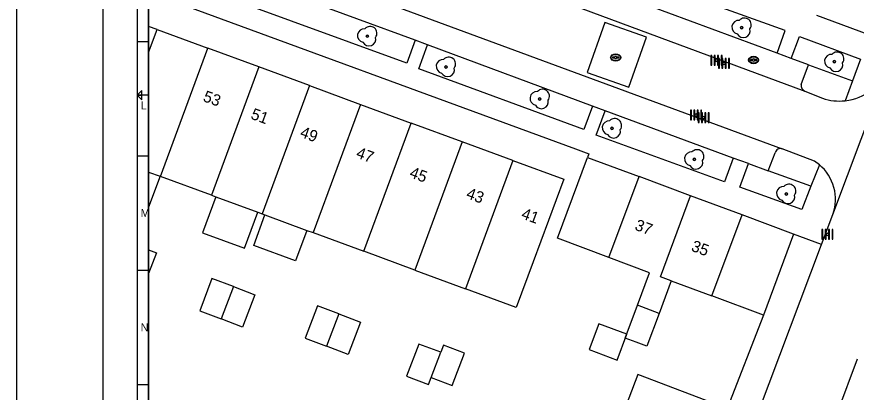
# Model space of a CAD drawing. Extents: x 192664 to 192925, y 446334 to 446521.
# Drawn here: x 192664.2 to 192737.6, y 446377 to 446409.8 of the extents above; entities that cross this region are included whole.
import ezdxf

# ---------------------------------------------------------------- set-up
doc = ezdxf.new("R2010")
doc.units = 0
for name, color, linetype in [('1010 viewport', 7, 'Continuous'), ('boom', 7, 'Continuous'), ('grens niveau plus 1', 7, 'Continuous'), ('huisnummerreeks BGT', 7, 'Continuous'), ('inspectie-   rioolput', 7, 'Continuous'), ('kant open verharding', 7, 'Continuous'), ('kant verharding', 7, 'Continuous'), ('kolk', 7, 'Continuous'), ('Luifel', 7, 'Continuous'), ('pand op maaiveld vlak', 7, 'Continuous'), ('verkeerseiland - berm', 7, 'Continuous'), ('X-XX-AL-TEKENBLAD-S', 7, 'Continuous'), ('X-XX-AL-TEKENBLAD_KADER-G', 7, 'Continuous')]:
    doc.layers.add(name, color=color, linetype=linetype)

msp = doc.modelspace()

# ---------------------------------------------------------------- linework, layer by layer
at = {"layer": '1010 viewport'}
msp.add_lwpolyline([(192675.743, 446509.756), (192860.643, 446509.756), (192860.643, 446345.556), (192675.743, 446345.556)], close=True, dxfattribs=at)
at = {"layer": 'boom'}
for centre in [(192727.554, 446408.855), (192694.841, 446408.12), (192735.654, 446405.881), (192701.719, 446405.432), (192709.917, 446402.624), (192716.227, 446400.059), (192723.418, 446397.341), (192731.456, 446394.317)]:
    msp.add_circle(centre, 0.1, dxfattribs=at)
for centre, radius, start, end in [((192727.304, 446408.905), 0.6, 85.13702, 257.75442), ((192727.804, 446409.105), 0.6, 323.54458, 138.4658), ((192694.591, 446408.17), 0.6, 85.13702, 257.75442), ((192695.091, 446408.37), 0.6, 323.54458, 138.4658), ((192727.704, 446408.605), 0.6, 208.50578, 13.83556), ((192727.554, 446408.855), 0.1, 0, 180), ((192727.554, 446408.855), 0.1, 180, 0), ((192694.991, 446407.87), 0.6, 208.50578, 13.83556), ((192694.841, 446408.12), 0.1, 0, 180), ((192694.841, 446408.12), 0.1, 180, 0), ((192735.404, 446405.931), 0.6, 85.13702, 257.75442), ((192735.904, 446406.131), 0.6, 323.54458, 138.4658), ((192701.469, 446405.482), 0.6, 85.13702, 257.75442), ((192701.969, 446405.682), 0.6, 323.54458, 138.4658), ((192735.804, 446405.631), 0.6, 208.50578, 13.83556), ((192735.654, 446405.881), 0.1, 0, 180), ((192735.654, 446405.881), 0.1, 180, 0), ((192701.869, 446405.182), 0.6, 208.50578, 13.83556), ((192701.719, 446405.432), 0.1, 0, 180), ((192701.719, 446405.432), 0.1, 180, 0), ((192710.167, 446402.874), 0.6, 323.54458, 138.4658), ((192709.667, 446402.674), 0.6, 85.13702, 257.75442), ((192709.917, 446402.624), 0.1, 0, 180), ((192710.067, 446402.374), 0.6, 208.50578, 13.83556), ((192709.917, 446402.624), 0.1, 180, 0), ((192715.977, 446400.109), 0.6, 85.13702, 257.75442), ((192716.477, 446400.309), 0.6, 323.54458, 138.4658), ((192716.377, 446399.809), 0.6, 208.50578, 13.83556), ((192716.227, 446400.059), 0.1, 0, 180), ((192716.227, 446400.059), 0.1, 180, 0), ((192723.168, 446397.391), 0.6, 85.13702, 257.75442), ((192723.668, 446397.591), 0.6, 323.54458, 138.4658), ((192723.568, 446397.091), 0.6, 208.50578, 13.83556), ((192723.418, 446397.341), 0.1, 0, 180), ((192723.418, 446397.341), 0.1, 180, 0), ((192731.206, 446394.367), 0.6, 85.13702, 257.75442), ((192731.706, 446394.567), 0.6, 323.54458, 138.4658), ((192731.606, 446394.067), 0.6, 208.50578, 13.83556), ((192731.456, 446394.317), 0.1, 0, 180), ((192731.456, 446394.317), 0.1, 180, 0)]:
    msp.add_arc(centre, radius, start, end, dxfattribs=at)
at = {"layer": 'grens niveau plus 1'}
msp.add_lwpolyline([(192717.516, 446382.047), (192715.072, 446382.958), (192714.229, 446380.696), (192716.674, 446379.786), (192717.516, 446382.047)], dxfattribs=at)
at = {"layer": 'inspectie-   rioolput'}
for p, q in [((192716.461, 446406.292), (192716.304, 446406.292)), ((192716.304, 446406.218), (192716.461, 446406.218)), ((192716.804, 446406.292), (192716.647, 446406.292)), ((192716.647, 446406.218), (192716.804, 446406.218)), ((192728.513, 446406.072), (192728.356, 446406.072)), ((192728.356, 446405.997), (192728.513, 446405.997)), ((192728.856, 446406.072), (192728.699, 446406.072)), ((192728.699, 446405.997), (192728.856, 446405.997))]:
    msp.add_line(p, q, dxfattribs=at)
for centre, radius, start, end in [((192716.554, 446406.255), 0.1, 0, 180), ((192716.304, 446406.255), 0.0375, 90, 270), ((192716.554, 446406.255), 0.1, 157.97569, 180), ((192716.554, 446406.255), 0.1, 180, 202.02431), ((192716.554, 446406.255), 0.1, 180, 0), ((192716.554, 446406.255), 0.1, 0, 22.02431), ((192716.554, 446406.255), 0.1, 337.97569, 0), ((192716.804, 446406.255), 0.0375, 270, 90), ((192728.356, 446406.034), 0.0375, 90, 270), ((192728.606, 446406.034), 0.1, 0, 180), ((192728.606, 446406.034), 0.1, 157.97569, 180), ((192728.606, 446406.034), 0.1, 180, 202.02431), ((192728.606, 446406.034), 0.1, 180, 0), ((192728.606, 446406.034), 0.1, 0, 22.02431), ((192728.606, 446406.034), 0.1, 337.97569, 0), ((192728.856, 446406.034), 0.0375, 270, 90)]:
    msp.add_arc(centre, radius, start, end, dxfattribs=at)
for centre, major_axis, ratio in [((192716.554, 446406.255), (-0.442, 0), 0.73911), ((192716.554, 446406.255), (-0.392, 0), 0.689655), ((192728.606, 446406.034), (-0.442, 0), 0.73911), ((192728.606, 446406.034), (-0.392, 0), 0.689655)]:
    msp.add_ellipse(centre, major_axis=major_axis, ratio=ratio, dxfattribs=at)
at = {"layer": 'kant open verharding'}
for p, q in [((192734.543, 446389.88), (192735.54, 446392.53)), ((192734.543, 446389.88), (192732.105, 446390.808)), ((192728.589, 446374.052), (192734.543, 446389.88)), ((192729.467, 446383.724), (192726.296, 446375.548))]:
    msp.add_line(p, q, dxfattribs=at)
for points in [[(192675.743, 446411.995), (192713.029, 446398.263), (192714.204, 446397.83), (192714.097, 446397.514)], [(192719.251, 446408.036), (192715.613, 446409.33), (192714.055, 446404.947), (192717.693, 446403.653), (192719.251, 446408.036)]]:
    msp.add_lwpolyline(points, dxfattribs=at)
for centre, radius, start, end in [((192736.087, 446407.003), 4.557, 276.55625, 339.08322), ((192731.81, 446393.843), 3.954, 340.60439, 49.92149)]:
    msp.add_arc(centre, radius, start, end, dxfattribs=at)
at = {"layer": 'kant verharding'}
for p, q in [((192675.743, 446424.623), (192733.082, 446403.313)), ((192675.743, 446418.762), (192731.114, 446398.266)), ((192700.122, 446407.353), (192699.029, 446407.759)), ((192731.902, 446406.177), (192730.661, 446406.636)), ((192735.54, 446392.53), (192740.343, 446405.376)), ((192715.622, 446401.596), (192714.516, 446402.006)), ((192728.147, 446396.977), (192726.814, 446397.454)), ((192737.657, 446379.855), (192731.919, 446364.598))]:
    msp.add_line(p, q, dxfattribs=at)
at = {"layer": 'kolk'}
for points in [[(192724.953, 446406.009), (192724.953, 446406.434), (192724.868, 446406.434), (192724.868, 446406.009), (192724.868, 446405.584), (192724.953, 446405.584)], [(192725.251, 446406.009), (192725.251, 446406.434), (192725.166, 446406.434), (192725.166, 446406.009), (192725.166, 446405.584), (192725.251, 446405.584)], [(192725.548, 446406.009), (192725.548, 446406.434), (192725.463, 446406.434), (192725.463, 446406.009), (192725.463, 446405.584), (192725.548, 446405.584)], [(192725.846, 446406.009), (192725.846, 446406.434), (192725.761, 446406.434), (192725.761, 446406.009), (192725.761, 446405.584), (192725.846, 446405.584)], [(192725.613, 446405.743), (192725.613, 446406.168), (192725.528, 446406.168), (192725.528, 446405.743), (192725.528, 446405.318), (192725.613, 446405.318)], [(192725.911, 446405.743), (192725.911, 446406.168), (192725.826, 446406.168), (192725.826, 446405.743), (192725.826, 446405.318), (192725.911, 446405.318)], [(192726.208, 446405.743), (192726.208, 446406.168), (192726.123, 446406.168), (192726.123, 446405.743), (192726.123, 446405.318), (192726.208, 446405.318)], [(192726.506, 446405.743), (192726.506, 446406.168), (192726.421, 446406.168), (192726.421, 446405.743), (192726.421, 446405.318), (192726.506, 446405.318)], [(192723.173, 446401.218), (192723.173, 446401.643), (192723.088, 446401.643), (192723.088, 446401.218), (192723.088, 446400.793), (192723.173, 446400.793)], [(192723.471, 446401.218), (192723.471, 446401.643), (192723.386, 446401.643), (192723.386, 446401.218), (192723.386, 446400.793), (192723.471, 446400.793)], [(192723.768, 446401.218), (192723.768, 446401.643), (192723.683, 446401.643), (192723.683, 446401.218), (192723.683, 446400.793), (192723.768, 446400.793)], [(192723.836, 446401.002), (192723.836, 446401.427), (192723.751, 446401.427), (192723.751, 446401.002), (192723.751, 446400.577), (192723.836, 446400.577)], [(192724.066, 446401.218), (192724.066, 446401.643), (192723.981, 446401.643), (192723.981, 446401.218), (192723.981, 446400.793), (192724.066, 446400.793)], [(192724.134, 446401.002), (192724.134, 446401.427), (192724.049, 446401.427), (192724.049, 446401.002), (192724.049, 446400.577), (192724.134, 446400.577)], [(192724.431, 446401.002), (192724.431, 446401.427), (192724.346, 446401.427), (192724.346, 446401.002), (192724.346, 446400.577), (192724.431, 446400.577)], [(192724.729, 446401.002), (192724.729, 446401.427), (192724.644, 446401.427), (192724.644, 446401.002), (192724.644, 446400.577), (192724.729, 446400.577)], [(192734.65, 446390.779), (192734.65, 446391.204), (192734.565, 446391.204), (192734.565, 446390.779), (192734.565, 446390.354), (192734.65, 446390.354)], [(192734.948, 446390.779), (192734.948, 446391.204), (192734.863, 446391.204), (192734.863, 446390.779), (192734.863, 446390.354), (192734.948, 446390.354)], [(192735.245, 446390.779), (192735.245, 446391.204), (192735.16, 446391.204), (192735.16, 446390.779), (192735.16, 446390.354), (192735.245, 446390.354)], [(192735.543, 446390.779), (192735.543, 446391.204), (192735.458, 446391.204), (192735.458, 446390.779), (192735.458, 446390.354), (192735.543, 446390.354)]]:
    msp.add_lwpolyline(points, close=True, dxfattribs=at)
for centre, start, end in [((192725.357, 446406.009), 0, 180), ((192725.357, 446406.009), 180, 0), ((192726.017, 446405.743), 0, 180), ((192726.017, 446405.743), 180, 0), ((192723.577, 446401.218), 0, 180), ((192723.577, 446401.218), 180, 0), ((192724.24, 446401.002), 0, 180), ((192724.24, 446401.002), 180, 0), ((192735.054, 446390.779), 0, 180), ((192735.054, 446390.779), 180, 0)]:
    msp.add_arc(centre, 0.1, start, end, dxfattribs=at)
at = {"layer": 'Luifel'}
msp.add_line((192676.742, 446395.864), (192675.743, 446393.155), dxfattribs=at)
for points in [[(192681.619, 446394.065), (192680.458, 446390.919), (192684.13, 446389.564), (192685.291, 446392.711)], [(192689.572, 446391.132), (192688.588, 446388.464), (192684.925, 446389.814), (192685.908, 446392.483)]]:
    msp.add_lwpolyline(points, dxfattribs=at)
at = {"layer": 'pand op maaiveld vlak'}
for p, q in [((192676.487, 446408.706), (192675.743, 446408.98)), ((192675.743, 446406.689), (192676.487, 446408.706)), ((192676.487, 446408.706), (192680.928, 446407.068)), ((192676.789, 446395.847), (192680.928, 446407.068)), ((192685.368, 446405.43), (192680.928, 446407.068)), ((192685.368, 446405.43), (192681.229, 446394.209)), ((192689.808, 446403.792), (192685.368, 446405.43)), ((192689.808, 446403.792), (192685.669, 446392.571)), ((192689.808, 446403.792), (192694.248, 446402.155)), ((192694.248, 446402.155), (192690.11, 446390.934)), ((192694.248, 446402.155), (192698.688, 446400.517)), ((192694.55, 446389.296), (192698.688, 446400.517)), ((192703.129, 446398.879), (192698.688, 446400.517)), ((192703.129, 446398.879), (192698.99, 446387.658)), ((192707.569, 446397.242), (192703.129, 446398.879)), ((192714.097, 446397.514), (192718.599, 446395.838)), ((192707.569, 446397.242), (192703.43, 446386.021)), ((192675.743, 446396.232), (192676.742, 446395.864)), ((192676.742, 446395.864), (192676.789, 446395.847)), ((192681.229, 446394.209), (192676.789, 446395.847)), ((192715.962, 446388.755), (192718.599, 446395.838)), ((192723.101, 446394.161), (192718.599, 446395.838)), ((192681.229, 446394.209), (192681.619, 446394.065)), ((192681.619, 446394.065), (192685.291, 446392.711)), ((192727.603, 446392.484), (192723.101, 446394.161)), ((192685.291, 446392.711), (192685.669, 446392.571)), ((192685.669, 446392.571), (192685.908, 446392.483)), ((192685.908, 446392.483), (192689.572, 446391.132)), ((192724.965, 446385.4), (192727.603, 446392.484)), ((192732.105, 446390.808), (192727.603, 446392.484)), ((192689.572, 446391.132), (192690.11, 446390.934)), ((192690.11, 446390.934), (192694.55, 446389.296)), ((192732.105, 446390.808), (192729.467, 446383.724)), ((192698.99, 446387.658), (192694.55, 446389.296)), ((192698.99, 446387.658), (192703.43, 446386.021)), ((192721.407, 446386.724), (192720.343, 446383.867)), ((192721.407, 446386.724), (192724.965, 446385.4)), ((192683.154, 446386.21), (192682.08, 446383.388)), ((192729.467, 446383.724), (192724.965, 446385.4)), ((192720.343, 446383.867), (192718.456, 446384.57)), ((192692.365, 446383.812), (192691.291, 446380.989)), ((192700.434, 446378.254), (192701.268, 446380.461))]:
    msp.add_line(p, q, dxfattribs=at)
for points in [[(192738.776, 446408.675), (192738.63, 446408.277), (192734.126, 446409.932)], [(192715.962, 446388.755), (192711.461, 446390.434), (192714.097, 446397.514)], [(192707.569, 446397.242), (192712.009, 446395.604), (192709.342, 446388.371), (192707.87, 446384.383), (192703.43, 446386.021)], [(192721.407, 446386.724), (192720.462, 446387.076), (192723.101, 446394.161)], [(192675.743, 446389.434), (192676.43, 446389.173), (192675.743, 446387.368)], [(192718.456, 446384.57), (192719.52, 446387.428), (192715.962, 446388.755)], [(192683.154, 446386.21), (192681.275, 446386.925), (192680.201, 446384.102), (192682.08, 446383.388)], [(192683.154, 446386.21), (192685.032, 446385.495), (192683.958, 446382.673), (192682.08, 446383.388)], [(192692.365, 446383.812), (192690.486, 446384.526), (192689.412, 446381.704), (192691.291, 446380.989)], [(192720.343, 446383.867), (192719.279, 446381.008), (192718.334, 446381.36), (192717.391, 446381.711), (192718.456, 446384.57)], [(192692.365, 446383.812), (192694.243, 446383.097), (192693.169, 446380.274), (192691.291, 446380.989)], [(192701.268, 446380.461), (192699.351, 446381.186), (192698.283, 446378.361), (192700.201, 446377.636), (192700.434, 446378.254)], [(192700.434, 446378.254), (192702.277, 446377.557), (192703.344, 446380.382), (192701.502, 446381.078), (192701.268, 446380.461)], [(192726.296, 446375.548), (192718.482, 446378.507), (192716.363, 446372.909)]]:
    msp.add_lwpolyline(points, dxfattribs=at)
at = {"layer": 'verkeerseiland - berm'}
for p, q in [((192699.029, 446407.759), (192683.929, 446413.333)), ((192730.661, 446406.636), (192719.304, 446410.835)), ((192714.516, 446402.006), (192700.122, 446407.353)), ((192733.417, 446405.619), (192731.902, 446406.177)), ((192732.774, 446403.888), (192733.417, 446405.619)), ((192733.417, 446405.619), (192737.245, 446404.209)), ((192737.245, 446404.209), (192736.607, 446402.476)), ((192733.082, 446403.313), (192734.635, 446402.685)), ((192726.814, 446397.454), (192715.622, 446401.596)), ((192729.893, 446396.351), (192730.476, 446397.916)), ((192728.147, 446396.977), (192729.893, 446396.351)), ((192734.356, 446396.869), (192733.62, 446394.998)), ((192733.62, 446394.998), (192729.893, 446396.351))]:
    msp.add_line(p, q, dxfattribs=at)
for points in [[(192699.029, 446407.759), (192698.296, 446405.758), (192683.182, 446411.296), (192683.929, 446413.333)], [(192730.661, 446406.636), (192731.377, 446408.627), (192719.987, 446412.729), (192719.304, 446410.835)], [(192731.902, 446406.177), (192732.604, 446408.083), (192737.948, 446406.115), (192737.245, 446404.209)], [(192714.516, 446402.006), (192713.762, 446399.96), (192699.355, 446405.274), (192700.122, 446407.353)], [(192726.814, 446397.454), (192726.067, 446395.39), (192714.846, 446399.456), (192715.622, 446401.596)], [(192734.356, 446396.869), (192733.926, 446397.184), (192731.114, 446398.266)], [(192733.62, 446394.998), (192732.813, 446392.945), (192727.395, 446394.907), (192728.147, 446396.977)]]:
    msp.add_lwpolyline(points, dxfattribs=at)
for centre, radius, start, end in [((192733.31, 446403.805), 0.543, 171.2346, 245.11705), ((192736.09, 446407.009), 4.562, 251.39698, 276.50335), ((192730.97, 446397.772), 0.514, 73.73617, 163.76124)]:
    msp.add_arc(centre, radius, start, end, dxfattribs=at)
at = {"layer": 'X-XX-AL-TEKENBLAD-S'}
for p, q in [((192671.743, 446511.756), (192671.743, 446343.556)), ((192674.743, 446510.756), (192674.743, 446344.556)), ((192674.743, 446407.656), (192675.743, 446407.656)), ((192675.143, 446402.956), (192674.743, 446402.956)), ((192674.743, 446402.956), (192675.143, 446402.956)), ((192675.743, 446402.956), (192674.743, 446402.956)), ((192674.743, 446397.656), (192675.743, 446397.656)), ((192674.743, 446387.656), (192675.743, 446387.656)), ((192674.743, 446377.656), (192675.743, 446377.656))]:
    msp.add_line(p, q, dxfattribs=at)
msp.add_lwpolyline([(192675.743, 446345.556), (192907.543, 446345.556), (192907.543, 446509.756), (192675.743, 446509.756)], close=True, dxfattribs=at)
for points in [[(192675.143, 446402.956), (192675.143, 446403.356), (192674.743, 446402.956)], [(192674.743, 446402.956), (192675.143, 446402.556), (192675.143, 446402.956)]]:
    msp.add_lwpolyline(points, dxfattribs=at)
at = {"layer": 'X-XX-AL-TEKENBLAD_KADER-G'}
msp.add_lwpolyline([(192664.22, 446520.974), (192925.029, 446520.974), (192925.029, 446333.894), (192664.22, 446333.894)], close=True, dxfattribs=at)

# ---------------------------------------------------------------- texts
at = {"layer": 'huisnummerreeks BGT'}
for s, rotation, p in [('53', 339.8, (192680.423, 446402.458)), ('51', 339.8, (192684.597, 446400.917)), ('49', 339.8, (192688.897, 446399.331)), ('47', 339.8, (192693.797, 446397.524)), ('45', 339.8, (192698.464, 446395.803)), ('43', 339.8, (192703.42, 446393.975)), ('41', 339.8, (192708.233, 446392.2)), ('37', 339.6, (192718.152, 446391.203)), ('35', 339.6, (192723.079, 446389.367))]:
    msp.add_text(s, height=1, rotation=rotation, dxfattribs=at).set_placement(p)
at = {"layer": 'X-XX-AL-TEKENBLAD-S'}
for s, p in [('L', (192675.043, 446401.706)), ('M', (192675.043, 446392.306)), ('N', (192675.043, 446382.306))]:
    msp.add_text(s, height=0.7, dxfattribs=at).set_placement(p)

doc.saveas('drawing.dxf')
